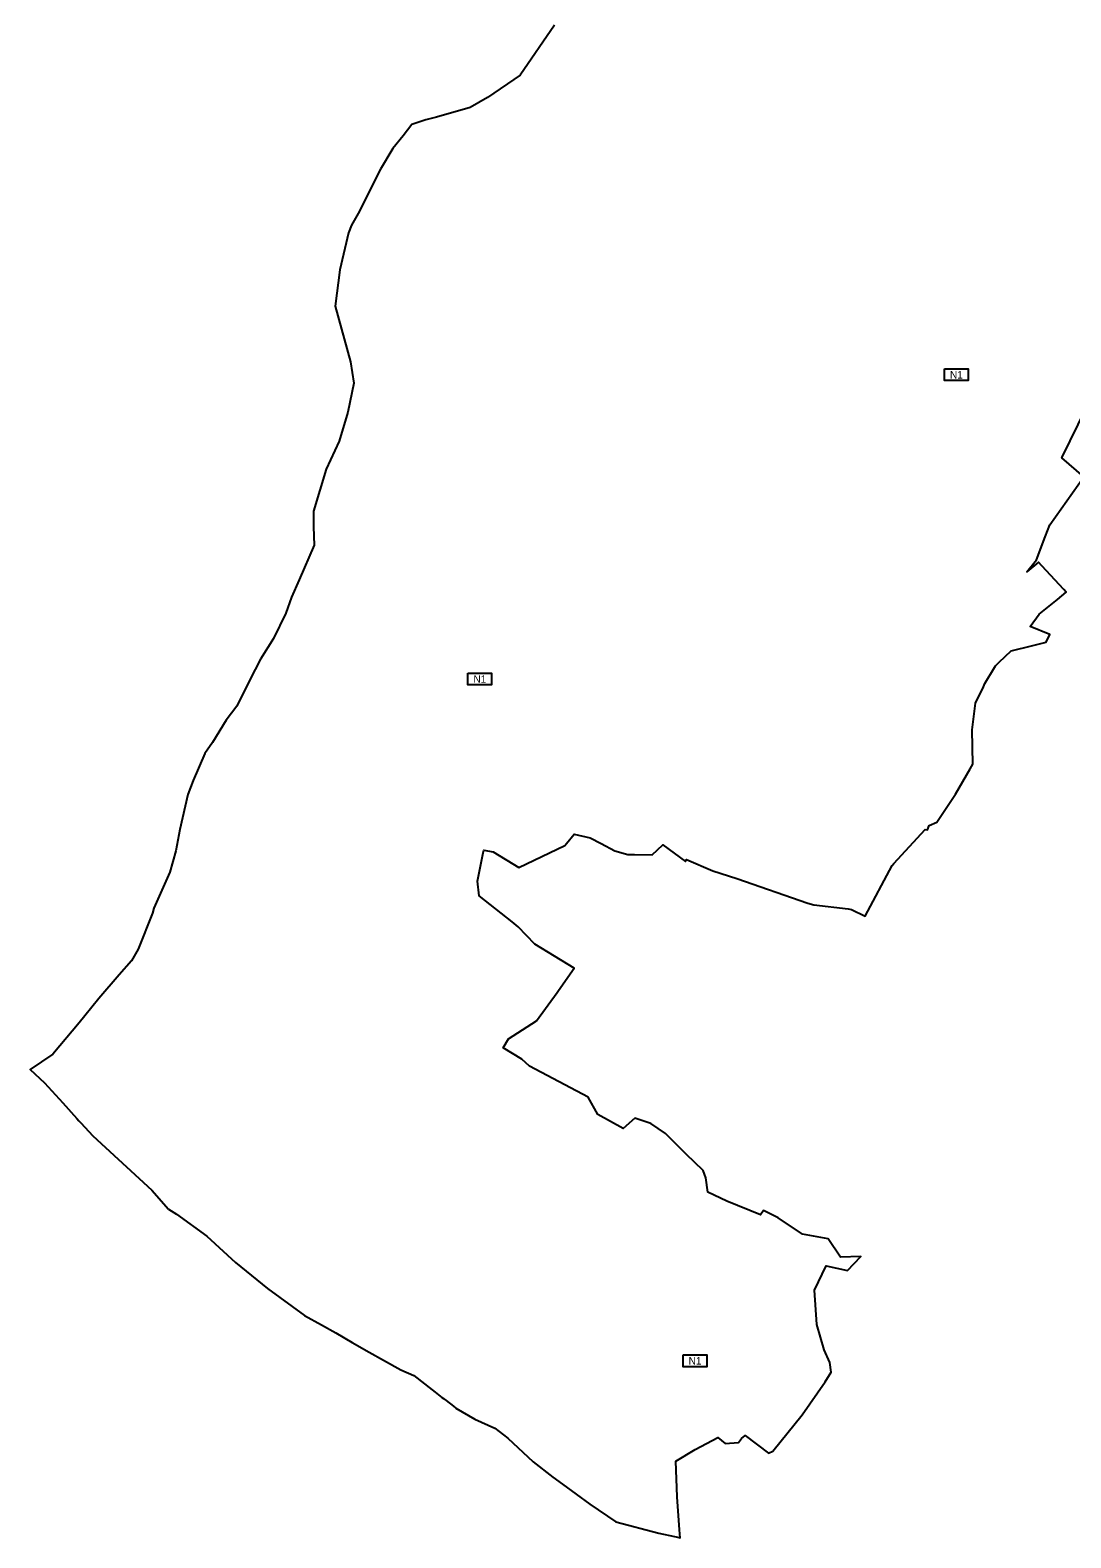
# Model space of a CAD drawing. Extents: x -545342 to -528609, y -1041871 to -1035695.
# Drawn here: x -545342 to -543958, y -1040078 to -1038074 of the extents above; entities that cross this region are included whole.
import ezdxf

# ---------------------------------------------------------------- set-up
doc = ezdxf.new("R2010")
doc.units = 0
for name, color, linetype in [('Vrstva 27', 7, 'Continuous'), ('Vrstva 5', 7, 'Continuous'), ('Vrstva66', 7, 'Continuous')]:
    doc.layers.add(name, color=color, linetype=linetype)

msp = doc.modelspace()

# ---------------------------------------------------------------- linework, layer by layer
at = {"layer": 'Vrstva 27'}
for points in [[(-544644.7, -1038066.8), (-544690.5, -1038133.3), (-544733.9, -1038163.3), (-544756.8, -1038176.3), (-544801.6, -1038189.5), (-544815.9, -1038192.9), (-544834.5, -1038199.3), (-544846.1, -1038214.3), (-544860, -1038230.9), (-544876.4, -1038258.7), (-544896.9, -1038299.8), (-544900.3, -1038306.4), (-544905.9, -1038317.4), (-544914.6, -1038332.8), (-544918.7, -1038343), (-544930.4, -1038392.2), (-544936.4, -1038440.7), (-544916.2, -1038514.7), (-544911.5, -1038543), (-544919.8, -1038581.8), (-544931.3, -1038620.2), (-544948.5, -1038657.6), (-544965.5, -1038713.1), (-544965.4, -1038734.1), (-544964.4, -1038758.3), (-544984.5, -1038804.7), (-544994.6, -1038827.5), (-545002, -1038848.8), (-545018.4, -1038882.7), (-545036, -1038909.9), (-545050.2, -1038937.3), (-545067.3, -1038972.6), (-545081.3, -1038991.1), (-545099.8, -1039020.9), (-545109.7, -1039035.5), (-545125.5, -1039071.5), (-545132.3, -1039089.8), (-545143.1, -1039136.7), (-545148.6, -1039164.9), (-545156.2, -1039193.4), (-545177.5, -1039241.2), (-545179.6, -1039247.7), (-545198.3, -1039295.8), (-545207.2, -1039311.1), (-545223.7, -1039329.9), (-545250.7, -1039361.1), (-545269.4, -1039384.5), (-545277.1, -1039393.5), (-545311.8, -1039435.4), (-545342.1, -1039455.5), (-545323.1, -1039473.5), (-545298.5, -1039500), (-545279.9, -1039520.9), (-545277.3, -1039523.9), (-545274.8, -1039526.7), (-545258.9, -1039543.8), (-545180.4, -1039616), (-545158.1, -1039641.5), (-545147.7, -1039648.1), (-545107.2, -1039677.4), (-545069.2, -1039712.3), (-545026.5, -1039747), (-544977.1, -1039782.6), (-544954.9, -1039795), (-544935.7, -1039805.6), (-544914, -1039818.7), (-544891.2, -1039831.7), (-544872.1, -1039842.3), (-544849.3, -1039854.8), (-544832, -1039862.5), (-544807.7, -1039881.4), (-544803.6, -1039884.5), (-544794.5, -1039891.6), (-544792.3, -1039893.2), (-544791.9, -1039893.6), (-544789, -1039895.8)], [(-544483.5, -1039976.4), (-544457.7, -1039961), (-544427.8, -1039945.1), (-544417.9, -1039953.1), (-544400, -1039951.6), (-544396.3, -1039946.3), (-544391.5, -1039942.2), (-544360.4, -1039965.7), (-544354.4, -1039963.2), (-544315.6, -1039914.8), (-544284.8, -1039870.8), (-544276.8, -1039858.3), (-544278.9, -1039845.1), (-544286.1, -1039828.4), (-544296.2, -1039794.7), (-544299.3, -1039749.2), (-544283.7, -1039716.8), (-544255.1, -1039723.1), (-544237.6, -1039704.1), (-544264.6, -1039705.1), (-544280.7, -1039680.6), (-544315.1, -1039674.7), (-544347.3, -1039653.1), (-544366.9, -1039643.1), (-544370.8, -1039648.7), (-544415.8, -1039630.9), (-544440.8, -1039618.8), (-544443.6, -1039599.7), (-544447.2, -1039589.8), (-544469.7, -1039568.1), (-544497.3, -1039540.7), (-544516.6, -1039527.5), (-544538.2, -1039520.2), (-544553.5, -1039534.2), (-544587.3, -1039515.6), (-544599.9, -1039492.4), (-544678.1, -1039451.3), (-544688.2, -1039442.1), (-544712.9, -1039426.7), (-544706.2, -1039415), (-544668.8, -1039391), (-544641.2, -1039353.1), (-544639.4, -1039350.6), (-544618.9, -1039320.7), (-544670.8, -1039288.9), (-544693.2, -1039265.8), (-544701.1, -1039259.5), (-544745, -1039224.6), (-544747.3, -1039205.4), (-544739.5, -1039167.7), (-544738.8, -1039163.9), (-544726.4, -1039166.3), (-544692.3, -1039187), (-544630.9, -1039158), (-544628.7, -1039155.2), (-544618.6, -1039142.6), (-544597.3, -1039147.8), (-544582.8, -1039155.3), (-544564.5, -1039164.8), (-544547.4, -1039169.8), (-544538.5, -1039169.8), (-544514.8, -1039170.1), (-544500.7, -1039156.9), (-544470.7, -1039179), (-544469.4, -1039176.4), (-544434.5, -1039191.7), (-544402.4, -1039201.7), (-544307.8, -1039234.6), (-544300.1, -1039236.8), (-544254.5, -1039242.2), (-544249.8, -1039242.8), (-544231.9, -1039251.9), (-544195.8, -1039184.6), (-544193.8, -1039181.7), (-544151.7, -1039136.6), (-544148.8, -1039136.8), (-544146.8, -1039131.4), (-544136.4, -1039126.7), (-544111.5, -1039089.6), (-544092.2, -1039056), (-544088.6, -1039049.8), (-544089.3, -1039004), (-544085, -1038968.5), (-544074.5, -1038946.6), (-544072.6, -1038942.6), (-544059.7, -1038921.2), (-544058.4, -1038918.9), (-544053.4, -1038914.1), (-544037.6, -1038898.9), (-544010.5, -1038892.2), (-544008.6, -1038891.8), (-543991.1, -1038887.5), (-543986.1, -1038877.4), (-544012.5, -1038866.5), (-544000.4, -1038850.3), (-543976.1, -1038830.8), (-543964.3, -1038820.8), (-543967.5, -1038817.5), (-543996.6, -1038785.8), (-544001, -1038781.1), (-544016.7, -1038793.7), (-544004, -1038777.8), (-543992.4, -1038747.4), (-543986.3, -1038731.5), (-543940.9, -1038667.7), (-543970, -1038642.4), (-543937.5, -1038575.3)], [(-544789, -1039895.8), (-544779.3, -1039903.3), (-544775.9, -1039905.9), (-544750.7, -1039920.8), (-544724.3, -1039932.5), (-544706.7, -1039945.8), (-544673.4, -1039977.3), (-544647.1, -1039997.5), (-544634, -1040007.1), (-544597.7, -1040033.6), (-544563.2, -1040057.3), (-544506.2, -1040072)], [(-544478.4, -1040067.8), (-544481.5, -1040023.9), (-544483.5, -1039976.4)], [(-544506.2, -1040072), (-544485.4, -1040076.6), (-544480.7, -1040077.7), (-544477.6, -1040078.4), (-544478.4, -1040067.8)]]:
    msp.add_lwpolyline(points, dxfattribs=at)
at = {"layer": 'Vrstva 5'}
for points in [[(-544126.4, -1038524.1), (-544094.7, -1038524.1), (-544094.7, -1038539.7), (-544126.4, -1038539.7)], [(-544760.1, -1038928.6), (-544728.4, -1038928.6), (-544728.4, -1038944.2), (-544760.1, -1038944.2)], [(-544473.9, -1039835.2), (-544442.2, -1039835.2), (-544442.2, -1039850.8), (-544473.9, -1039850.8)]]:
    msp.add_lwpolyline(points, close=True, dxfattribs=at)
at = {"layer": 'Vrstva66'}
msp.add_lwpolyline([(-544644.7, -1038066.8), (-544690.5, -1038133.3), (-544733.9, -1038163.3), (-544756.8, -1038176.3), (-544801.6, -1038189.5), (-544815.9, -1038192.9), (-544834.5, -1038199.3), (-544846.1, -1038214.3), (-544860, -1038230.9), (-544876.4, -1038258.7), (-544896.9, -1038299.8), (-544900.3, -1038306.4), (-544905.9, -1038317.4), (-544914.6, -1038332.8), (-544918.7, -1038343), (-544930.4, -1038392.2), (-544936.4, -1038440.7), (-544916.2, -1038514.7), (-544911.5, -1038543), (-544919.8, -1038581.8), (-544931.3, -1038620.2), (-544948.5, -1038657.6), (-544965.5, -1038713.1), (-544965.4, -1038734.1), (-544964.4, -1038758.3), (-544984.5, -1038804.7), (-544994.6, -1038827.5), (-545002, -1038848.8), (-545018.4, -1038882.7), (-545036, -1038909.9), (-545050.2, -1038937.3), (-545067.3, -1038972.6), (-545081.3, -1038991.1), (-545099.8, -1039020.9), (-545109.7, -1039035.5), (-545125.5, -1039071.5), (-545132.3, -1039089.8), (-545143.1, -1039136.7), (-545148.6, -1039164.9), (-545156.2, -1039193.4), (-545177.5, -1039241.2), (-545179.6, -1039247.7), (-545198.3, -1039295.8), (-545207.2, -1039311.1), (-545223.7, -1039329.9), (-545250.7, -1039361.1), (-545269.4, -1039384.5), (-545277.1, -1039393.5), (-545311.8, -1039435.4), (-545342.1, -1039455.5), (-545323.1, -1039473.5), (-545298.5, -1039500), (-545279.9, -1039520.9), (-545277.3, -1039523.9), (-545274.8, -1039526.7), (-545258.9, -1039543.8), (-545180.4, -1039616), (-545158.1, -1039641.5), (-545147.7, -1039648.1), (-545107.2, -1039677.4), (-545069.2, -1039712.3), (-545026.5, -1039747), (-544977.1, -1039782.6), (-544954.9, -1039795), (-544935.7, -1039805.6), (-544914, -1039818.7), (-544891.2, -1039831.7), (-544872.1, -1039842.3), (-544849.3, -1039854.8), (-544832, -1039862.5), (-544807.7, -1039881.4), (-544803.6, -1039884.5), (-544794.5, -1039891.6), (-544792.3, -1039893.2), (-544791.9, -1039893.6), (-544789, -1039895.8), (-544779.3, -1039903.3), (-544775.9, -1039905.9), (-544750.7, -1039920.8), (-544724.3, -1039932.5), (-544706.7, -1039945.8), (-544673.4, -1039977.3), (-544647.1, -1039997.5), (-544634, -1040007.1), (-544597.7, -1040033.6), (-544563.2, -1040057.3), (-544506.2, -1040072), (-544485.4, -1040076.6), (-544480.7, -1040077.7), (-544477.6, -1040078.4), (-544478.4, -1040067.8), (-544481.5, -1040023.9), (-544483.5, -1039976.4), (-544457.7, -1039961), (-544427.8, -1039945.1), (-544417.9, -1039953.1), (-544400, -1039951.6), (-544396.3, -1039946.3), (-544391.5, -1039942.2), (-544360.4, -1039965.7), (-544354.4, -1039963.2), (-544315.6, -1039914.8), (-544284.8, -1039870.8), (-544276.8, -1039858.3), (-544278.9, -1039845.1), (-544286.1, -1039828.4), (-544296.2, -1039794.7), (-544299.3, -1039749.2), (-544283.7, -1039716.8), (-544255.1, -1039723.1), (-544237.6, -1039704.1), (-544264.6, -1039705.1), (-544280.7, -1039680.6), (-544315.1, -1039674.7), (-544347.3, -1039653.1), (-544366.9, -1039643.1), (-544370.8, -1039648.7), (-544415.8, -1039630.9), (-544440.8, -1039618.8), (-544443.6, -1039599.7), (-544447.2, -1039589.8), (-544469.7, -1039568.1), (-544497.3, -1039540.7), (-544516.6, -1039527.5), (-544538.2, -1039520.2), (-544553.5, -1039534.2), (-544587.3, -1039515.6), (-544599.9, -1039492.4), (-544678.1, -1039451.3), (-544688.2, -1039442.1), (-544712.9, -1039426.7), (-544706.2, -1039415), (-544668.8, -1039391), (-544641.2, -1039353.1), (-544639.4, -1039350.6), (-544618.9, -1039320.7), (-544670.8, -1039288.9), (-544693.2, -1039265.8), (-544701.1, -1039259.5), (-544745, -1039224.6), (-544747.3, -1039205.4), (-544739.5, -1039167.7), (-544738.8, -1039163.9), (-544726.4, -1039166.3), (-544692.3, -1039187), (-544630.9, -1039158), (-544628.7, -1039155.2), (-544618.6, -1039142.6), (-544597.3, -1039147.8), (-544582.8, -1039155.3), (-544564.5, -1039164.8), (-544547.4, -1039169.8), (-544538.5, -1039169.8), (-544514.8, -1039170.1), (-544500.7, -1039156.9), (-544470.7, -1039179), (-544469.4, -1039176.4), (-544434.5, -1039191.7), (-544402.4, -1039201.7), (-544307.8, -1039234.6), (-544300.1, -1039236.8), (-544254.5, -1039242.2), (-544249.8, -1039242.8), (-544231.9, -1039251.9), (-544195.8, -1039184.6), (-544193.8, -1039181.7), (-544151.7, -1039136.6), (-544148.8, -1039136.8), (-544146.8, -1039131.4), (-544136.4, -1039126.7), (-544111.5, -1039089.6), (-544092.2, -1039056), (-544088.6, -1039049.8), (-544089.3, -1039004), (-544085, -1038968.5), (-544074.5, -1038946.6), (-544072.6, -1038942.6), (-544059.7, -1038921.2), (-544058.4, -1038918.9), (-544053.4, -1038914.1), (-544037.6, -1038898.9), (-544010.5, -1038892.2), (-544008.6, -1038891.8), (-543991.1, -1038887.5), (-543986.1, -1038877.4), (-544012.5, -1038866.5), (-544000.4, -1038850.3), (-543976.1, -1038830.8), (-543964.3, -1038820.8), (-543967.5, -1038817.5), (-543996.6, -1038785.8), (-544001, -1038781.1), (-544016.7, -1038793.7), (-544004, -1038777.8), (-543992.4, -1038747.4), (-543986.3, -1038731.5), (-543940.9, -1038667.7), (-543970, -1038642.4), (-543937.5, -1038575.3)], dxfattribs=at)

# ---------------------------------------------------------------- texts
at = {"layer": 'Vrstva 5'}
for p in [(-544118.9, -1038536.9), (-544752.6, -1038941.4), (-544466.5, -1039848)]:
    msp.add_text('N1', height=10, dxfattribs=at).set_placement(p)

doc.saveas('drawing.dxf')
